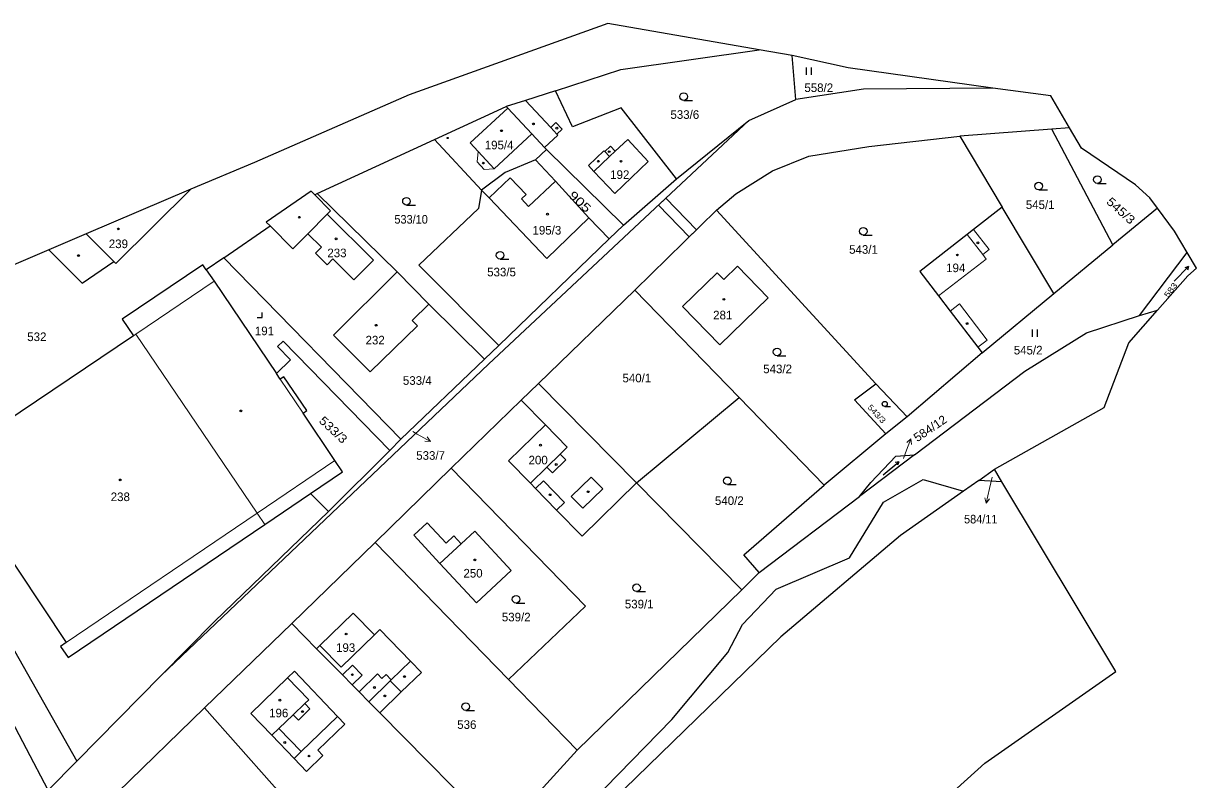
# Model space of a CAD drawing. Extents: x -754445 to -751443, y -1030748 to -1028224.
# Drawn here: x -752550.8 to -752319, y -1028439.3 to -1028289.9 of the extents above; entities that cross this region are included whole.
import ezdxf
from ezdxf.enums import TextEntityAlignment as Align

# ---------------------------------------------------------------- set-up
doc = ezdxf.new("R2010")
doc.units = 0
doc.header["$LTSCALE"] = 0.68
for name, color, linetype, lineweight in [('1', 7, 'Continuous', 25), ('13', 7, 'Continuous', 13), ('3', 7, 'Continuous', 25), ('4', 7, 'Continuous', 13), ('5', 7, 'Continuous', 25), ('7', 7, 'Continuous', 13)]:
    doc.layers.add(name, color=color, linetype=linetype, lineweight=lineweight)
doc.layers.add('2', color=7, linetype='Continuous')

msp = doc.modelspace()

# ---------------------------------------------------------------- linework, layer by layer
at = {"layer": '1'}
for p, q in [((-752398.89, -1028296.26), (-752405.38, -1028295.13)), ((-752387.84, -1028298.72), (-752398.89, -1028296.26)), ((-752359.23, -1028302.73), (-752387.84, -1028298.72)), ((-752469.6, -1028312.88), (-752455.4, -1028306.37)), ((-752469.6, -1028312.88), (-752460.28, -1028322.85)), ((-752449.62, -1028316.91), (-752447.46, -1028314.86)), ((-752455.63, -1028319.39), (-752460.28, -1028322.85)), ((-752476.98, -1028339.02), (-752492.8, -1028323.52)), ((-752430.02, -1028342.61), (-752413.84, -1028326.86)), ((-752511.23, -1028336.26), (-752502.09, -1028329.94)), ((-752435.06, -1028332.52), (-752439.06, -1028328.33)), ((-752432.25, -1028329.82), (-752435.06, -1028332.52)), ((-752456.89, -1028353.54), (-752435.06, -1028332.52)), ((-752330.24, -1028347.65), (-752320.82, -1028335.2)), ((-752470.68, -1028345.38), (-752476.98, -1028339.02)), ((-752430.02, -1028342.61), (-752449.02, -1028361.08)), ((-752330.24, -1028347.65), (-752326.68, -1028346.62)), ((-752456.89, -1028353.54), (-752459.73, -1028356.27)), ((-752386.55, -1028364.28), (-752382.36, -1028361.14)), ((-752452.44, -1028364.4), (-752466.28, -1028377.84)), ((-752392.57, -1028381.17), (-752409.39, -1028363.85)), ((-752380.37, -1028371.03), (-752386.55, -1028364.28)), ((-752490.54, -1028386.35), (-752478.41, -1028374.3)), ((-752374.74, -1028375.19), (-752385.55, -1028383.4)), ((-752466.28, -1028377.84), (-752481.34, -1028392.48)), ((-752357.44, -1028380.49), (-752358.91, -1028378.04)), ((-752405.38, -1028398.45), (-752385.55, -1028383.4)), ((-752481.34, -1028392.48), (-752497.81, -1028408.48)), ((-752454.95, -1028419.58), (-752481.34, -1028392.48)), ((-752408.87, -1028401.85), (-752405.38, -1028398.45)), ((-752540.27, -1028435.69), (-752523.59, -1028418.77)), ((-752441.39, -1028433.5), (-752454.95, -1028419.58)), ((-752532.24, -1028441.9), (-752515.04, -1028425.14)), ((-752456.6, -1028450.26), (-752441.39, -1028433.5)), ((-752540.27, -1028435.69), (-752545.95, -1028441.45))]:
    msp.add_line(p, q, dxfattribs=at)
for points in [[(-752405.38, -1028295.13), (-752435.3, -1028289.94), (-752474.61, -1028304.07), (-752505.18, -1028317.44), (-752517.76, -1028322.7)], [(-752445.69, -1028303.22), (-752432.77, -1028299.03), (-752405.38, -1028295.13)], [(-752421.72, -1028320.62), (-752407.46, -1028309.12), (-752398.17, -1028304.98), (-752398.89, -1028296.26)], [(-752445.69, -1028303.22), (-752451.62, -1028305.14), (-752455.4, -1028306.37)], [(-752421.72, -1028320.62), (-752432.69, -1028306.58), (-752442.28, -1028310.36), (-752445.69, -1028303.22)], [(-752359.23, -1028302.73), (-752384.8, -1028302.94), (-752398.17, -1028304.98)], [(-752344.05, -1028310.59), (-752347.75, -1028304.24), (-752359.23, -1028302.73)], [(-752455.4, -1028306.37), (-752455.1, -1028306.68), (-752450.34, -1028311.78), (-752447.82, -1028314.48), (-752447.46, -1028314.86), (-752432.25, -1028329.82), (-752421.72, -1028320.62)], [(-752523.59, -1028418.77), (-752458.89, -1028357.28), (-752407.46, -1028309.12)], [(-752347.15, -1028343.32), (-752335.5, -1028333.7), (-752347.54, -1028310.85), (-752365.74, -1028312.22), (-752357.35, -1028326.26)], [(-752326.68, -1028326.41), (-752328.18, -1028324.37), (-752331.04, -1028321.82), (-752341.71, -1028314.6), (-752344.05, -1028310.59), (-752347.54, -1028310.85)], [(-752493.24, -1028323.83), (-752492.8, -1028323.52), (-752469.6, -1028312.88)], [(-752413.84, -1028326.86), (-752410.04, -1028323.61), (-752402.77, -1028319.05), (-752395.61, -1028316.19), (-752383.74, -1028314.26), (-752365.74, -1028312.22)], [(-752439.06, -1028328.33), (-752445.67, -1028321.09), (-752449.62, -1028316.91), (-752455.63, -1028319.39)], [(-752517.76, -1028322.7), (-752538.45, -1028331.51), (-752545.81, -1028334.65)], [(-752545.81, -1028334.65), (-752539.2, -1028341.26), (-752532.94, -1028336.98), (-752532.55, -1028337.37), (-752517.76, -1028322.7)], [(-752460.28, -1028322.85), (-752460.92, -1028326.51), (-752472.66, -1028337.69), (-752456.89, -1028353.54)], [(-752439.06, -1028328.33), (-752447.39, -1028336.38), (-752458.79, -1028324.4), (-752460.28, -1028322.85)], [(-752493.24, -1028323.83), (-752493.97, -1028323.1), (-752502.86, -1028329.17), (-752502.09, -1028329.94)], [(-752502.09, -1028329.94), (-752497.59, -1028334.44), (-752494.6, -1028331.48), (-752491.95, -1028334.14), (-752493.11, -1028335.3), (-752490.81, -1028337.6), (-752489.65, -1028336.44), (-752485.51, -1028340.57), (-752481.66, -1028336.71), (-752490.77, -1028327.61), (-752490.11, -1028326.95), (-752493.24, -1028323.83)], [(-752413.84, -1028326.86), (-752382.36, -1028361.14), (-752376.18, -1028367.69)], [(-752357.35, -1028326.26), (-752363.03, -1028330.68), (-752364.29, -1028331.67), (-752373.64, -1028338.95), (-752369.96, -1028343.75), (-752367.65, -1028346.76), (-752362.18, -1028353.9), (-752361.32, -1028355.02)], [(-752361.32, -1028355.02), (-752347.15, -1028343.32), (-752357.35, -1028326.26)], [(-752320.82, -1028335.2), (-752323.33, -1028330.97), (-752326.68, -1028326.41), (-752335.5, -1028333.7)], [(-752545.81, -1028334.65), (-752556.51, -1028339.21), (-752568.95, -1028351.49), (-752579.96, -1028370.78)], [(-752500.83, -1028359.1), (-752498.05, -1028356.39), (-752500.59, -1028353.77), (-752499.48, -1028352.69), (-752478.41, -1028374.3), (-752476.21, -1028372.11), (-752511.23, -1028336.26), (-752514.69, -1028338.65)], [(-752326.68, -1028346.62), (-752320.66, -1028339.81), (-752318.96, -1028338.32), (-752320.82, -1028335.2)], [(-752514.69, -1028338.65), (-752515.41, -1028337.64), (-752531.29, -1028348.38), (-752529.08, -1028351.68), (-752561.06, -1028373.16), (-752562.37, -1028371.21), (-752567.41, -1028374.68), (-752566.1, -1028376.62), (-752542.38, -1028412.28), (-752543.51, -1028413.04), (-752542.01, -1028415.25), (-752503.1, -1028388.94), (-752494.07, -1028382.8)], [(-752514.69, -1028338.65), (-752513.11, -1028340.87), (-752500.83, -1028359.1)], [(-752476.98, -1028339.02), (-752489.54, -1028351.55), (-752482.27, -1028358.76), (-752472.95, -1028349.66), (-752473.98, -1028348.6), (-752470.68, -1028345.38)], [(-752429.66, -1028380.74), (-752409.39, -1028363.85), (-752430.02, -1028342.61)], [(-752476.21, -1028372.11), (-752459.73, -1028356.27), (-752470.68, -1028345.38)], [(-752374.74, -1028375.19), (-752352.93, -1028358.63), (-752340.68, -1028351.04), (-752330.24, -1028347.65)], [(-752337.25, -1028365.83), (-752332.34, -1028353.02), (-752326.68, -1028346.62)], [(-752361.32, -1028355.02), (-752376.18, -1028367.69), (-752380.37, -1028371.03), (-752392.57, -1028381.17)], [(-752494.07, -1028382.8), (-752487.77, -1028378.51), (-752489.26, -1028376.3), (-752495.53, -1028366.91), (-752494.82, -1028366.42), (-752499.36, -1028359.74), (-752500.07, -1028360.23), (-752500.83, -1028359.1)], [(-752429.66, -1028380.74), (-752449.02, -1028361.08), (-752452.44, -1028364.4)], [(-752452.44, -1028364.4), (-752447.67, -1028369.27), (-752454.94, -1028376.39), (-752450.62, -1028380.8), (-752449.61, -1028381.84), (-752445.45, -1028386.08), (-752440.39, -1028391.25), (-752429.66, -1028380.74)], [(-752362.02, -1028380.23), (-752358.91, -1028378.04), (-752337.25, -1028365.83)], [(-752584.13, -1028375.9), (-752579.37, -1028374.82), (-752573.06, -1028377.89), (-752540.27, -1028435.69)], [(-752385.55, -1028383.4), (-752383.32, -1028380.64), (-752378.37, -1028375.43), (-752374.74, -1028375.19)], [(-752466.28, -1028377.84), (-752439.77, -1028405.07), (-752454.95, -1028419.58)], [(-752529.24, -1028502.86), (-752525.84, -1028499.97), (-752501.12, -1028496.21), (-752473.43, -1028475.03), (-752455.24, -1028458.91), (-752438.5, -1028443.67), (-752422.66, -1028427.47), (-752411.63, -1028414.26), (-752408.72, -1028408.7), (-752402.05, -1028401.7), (-752387.55, -1028395.51), (-752380.84, -1028384.53), (-752373.02, -1028380.06), (-752365.04, -1028382.36)], [(-752441.39, -1028433.5), (-752408.87, -1028401.85), (-752429.66, -1028380.74)], [(-752334.93, -1028417.99), (-752357.44, -1028380.49), (-752362.02, -1028380.23), (-752365.04, -1028382.36)], [(-752365.04, -1028382.36), (-752377.46, -1028391.11), (-752401.11, -1028411.16), (-752446.33, -1028455.06), (-752461.39, -1028474.9), (-752481.91, -1028492.23), (-752531.14, -1028512.51)], [(-752523.59, -1028418.77), (-752513.07, -1028408.1), (-752490.54, -1028386.35), (-752494.07, -1028382.8)], [(-752405.38, -1028398.45), (-752408.43, -1028394.94), (-752392.57, -1028381.17)], [(-752575.39, -1028472.41), (-752545.95, -1028441.45), (-752567.4, -1028400.59)], [(-752480.38, -1028426.15), (-752476.15, -1028422.03), (-752472.17, -1028418.16), (-752474.33, -1028415.93), (-752480.4, -1028409.7), (-752481.47, -1028410.75), (-752485.66, -1028406.45), (-752492.24, -1028412.86), (-752492.88, -1028413.48)], [(-752492.88, -1028413.48), (-752497.81, -1028408.48), (-752515.04, -1028425.14), (-752475.1, -1028470.2), (-752465.01, -1028461.38)], [(-752492.88, -1028413.48), (-752487.75, -1028418.68), (-752485.85, -1028420.6), (-752484.45, -1028422.03), (-752482.55, -1028423.95), (-752480.38, -1028426.15)], [(-752383.33, -1028456.44), (-752360.81, -1028436.09), (-752334.93, -1028417.99)], [(-752465.01, -1028461.38), (-752456.6, -1028450.26), (-752480.38, -1028426.15)]]:
    msp.add_lwpolyline(points, dxfattribs=at)
for points in [[(-752403.61, -1028344.14), (-752413.17, -1028353.43), (-752420.54, -1028345.85), (-752413.69, -1028339.22), (-752412.4, -1028340.55), (-752409.67, -1028337.91)], [(-752468.51, -1028396.62), (-752461.31, -1028404.4), (-752454.43, -1028398.04), (-752461.63, -1028390.26), (-752464.31, -1028392.73), (-752465.75, -1028391.18), (-752467.29, -1028392.6), (-752471.01, -1028388.58), (-752473.67, -1028391.04)], [(-752498.64, -1028419.21), (-752505.89, -1028426.26), (-752501.72, -1028430.6), (-752497.35, -1028435.15), (-752494.87, -1028437.73), (-752491.63, -1028434.61), (-752492.66, -1028433.53), (-752487.34, -1028428.39), (-752488.78, -1028426.87), (-752497.28, -1028417.89)]]:
    msp.add_lwpolyline(points, close=True, dxfattribs=at)
at = {"layer": '13'}
msp.add_lwpolyline([(-752417.82, -1028330.73), (-752423.83, -1028324.45), (-752425.29, -1028325.82), (-752419.25, -1028332.13)], close=True, dxfattribs=at)
at = {"layer": '3'}
for p, q in [((-752396.071, -1028300.11), (-752396.071, -1028298.61)), ((-752395.07, -1028300.11), (-752395.07, -1028298.61)), ((-752420.333, -1028305.13), (-752418.583, -1028305.13)), ((-752350.163, -1028322.82), (-752348.413, -1028322.82)), ((-752338.563, -1028321.55), (-752336.813, -1028321.55)), ((-752475.123, -1028325.83), (-752473.373, -1028325.83)), ((-752384.833, -1028331.75), (-752383.083, -1028331.75)), ((-752456.633, -1028336.5), (-752454.883, -1028336.5)), ((-752320.562, -1028337.98), (-752320.775, -1028338.684)), ((-752351.381, -1028351.88), (-752351.381, -1028350.38)), ((-752350.38, -1028351.88), (-752350.38, -1028350.38)), ((-752401.873, -1028355.59), (-752400.123, -1028355.59)), ((-752380.595, -1028365.63), (-752379.423, -1028365.63)), ((-752377.808, -1028376.535), (-752378.093, -1028377.213)), ((-752411.683, -1028381.06), (-752409.933, -1028381.06)), ((-752429.643, -1028402.18), (-752427.893, -1028402.18)), ((-752453.453, -1028404.47), (-752451.703, -1028404.47)), ((-752463.403, -1028425.67), (-752461.653, -1028425.67))]:
    msp.add_line(p, q, dxfattribs=at)
for points in [[(-752323.354, -1028340.872), (-752320.562, -1028337.98), (-752321.258, -1028338.217)], [(-752504.621, -1028348.06), (-752503.62, -1028348.06), (-752503.62, -1028347.06)], [(-752380.887, -1028379.119), (-752377.808, -1028376.535), (-752378.525, -1028376.698)]]:
    msp.add_lwpolyline(points, dxfattribs=at)
for centre, radius in [((-752420.3329, -1028304.3798), 0.75), ((-752338.5629, -1028320.7998), 0.75), ((-752350.1629, -1028322.0698), 0.75), ((-752475.1229, -1028325.0798), 0.75), ((-752384.8329, -1028330.9998), 0.75), ((-752456.6329, -1028335.7498), 0.75), ((-752401.8729, -1028354.8398), 0.75), ((-752380.5952, -1028365.1274), 0.5025), ((-752411.6829, -1028380.3098), 0.75), ((-752429.6429, -1028401.4298), 0.75), ((-752453.4529, -1028403.7198), 0.75), ((-752463.4029, -1028424.9198), 0.75)]:
    msp.add_circle(centre, radius, dxfattribs=at)
at = {"layer": '4'}
for p, q in [((-752455.1, -1028306.68), (-752462.53, -1028313.55)), ((-752451.62, -1028305.14), (-752446.62, -1028310.48)), ((-752446.62, -1028310.48), (-752445.6, -1028309.53)), ((-752446.62, -1028310.48), (-752445.39, -1028311.8)), ((-752445.6, -1028309.53), (-752444.37, -1028310.84)), ((-752444.37, -1028310.84), (-752445.39, -1028311.8)), ((-752462.53, -1028313.55), (-752460.94, -1028315.27)), ((-752457.8, -1028318.68), (-752450.34, -1028311.78)), ((-752445.19, -1028312.02), (-752447.82, -1028314.48)), ((-752445.39, -1028311.8), (-752445.19, -1028312.02)), ((-752433.85, -1028315.2), (-752431.38, -1028312.89)), ((-752427.33, -1028317.22), (-752431.38, -1028312.89)), ((-752460.94, -1028315.27), (-752461.15, -1028317.3)), ((-752460.94, -1028315.27), (-752457.8, -1028318.68)), ((-752436.1, -1028315.08), (-752439.17, -1028318.01)), ((-752435.94, -1028315.24), (-752436.1, -1028315.08)), ((-752435.94, -1028315.24), (-752434.8, -1028314.18)), ((-752434.98, -1028316.25), (-752435.94, -1028315.24)), ((-752434.98, -1028316.25), (-752433.85, -1028315.2)), ((-752434.8, -1028314.18), (-752433.85, -1028315.2)), ((-752461.15, -1028317.3), (-752459.78, -1028318.79)), ((-752439.17, -1028318.01), (-752438.08, -1028319.16)), ((-752438.08, -1028319.16), (-752434.98, -1028316.25)), ((-752433.93, -1028323.51), (-752427.33, -1028317.22)), ((-752459.78, -1028318.79), (-752457.8, -1028318.68)), ((-752454.61, -1028320.44), (-752458.79, -1028324.4)), ((-752451.49, -1028323.74), (-752454.61, -1028320.44)), ((-752438.08, -1028319.16), (-752433.93, -1028323.51)), ((-752445.67, -1028321.09), (-752450.99, -1028326.13)), ((-752452.41, -1028324.62), (-752451.49, -1028323.74)), ((-752450.99, -1028326.13), (-752452.41, -1028324.62)), ((-752494.6, -1028331.48), (-752490.77, -1028327.61)), ((-752538.45, -1028331.51), (-752532.94, -1028336.98)), ((-752361.23, -1028335.61), (-752364.29, -1028331.67)), ((-752363.03, -1028330.68), (-752359.96, -1028334.62)), ((-752359.96, -1028334.62), (-752361.23, -1028335.61)), ((-752360.52, -1028336.51), (-752369.96, -1028343.75)), ((-752360.52, -1028336.51), (-752361.23, -1028335.61)), ((-752528.59, -1028351.35), (-752513.11, -1028340.87)), ((-752365.83, -1028345.36), (-752367.65, -1028346.76)), ((-752360.35, -1028352.5), (-752365.83, -1028345.36)), ((-752528.59, -1028351.35), (-752529.08, -1028351.68)), ((-752504.63, -1028386.68), (-752528.59, -1028351.35)), ((-752360.35, -1028352.5), (-752362.18, -1028353.9)), ((-752495.53, -1028366.91), (-752500.07, -1028360.23)), ((-752443.35, -1028373.68), (-752447.67, -1028369.27)), ((-752444.74, -1028375.04), (-752443.35, -1028373.68)), ((-752504.63, -1028386.68), (-752489.26, -1028376.3)), ((-752447.38, -1028377.63), (-752444.74, -1028375.04)), ((-752446.29, -1028378.75), (-752443.64, -1028376.16)), ((-752443.64, -1028376.16), (-752444.74, -1028375.04)), ((-752450.62, -1028380.8), (-752447.38, -1028377.63)), ((-752447.38, -1028377.63), (-752446.29, -1028378.75)), ((-752448.07, -1028380.33), (-752449.61, -1028381.84)), ((-752443.92, -1028384.57), (-752448.07, -1028380.33)), ((-752442.55, -1028383.42), (-752438.61, -1028379.56)), ((-752438.61, -1028379.56), (-752436.34, -1028381.89)), ((-752436.34, -1028381.89), (-752440.28, -1028385.74)), ((-752445.45, -1028386.08), (-752443.92, -1028384.57)), ((-752440.28, -1028385.74), (-752442.55, -1028383.42)), ((-752542.38, -1028412.28), (-752504.63, -1028386.68)), ((-752503.1, -1028388.94), (-752504.63, -1028386.68)), ((-752468.51, -1028396.62), (-752464.31, -1028392.73)), ((-752488.05, -1028417.16), (-752481.47, -1028410.75)), ((-752488.05, -1028417.16), (-752492.24, -1028412.86)), ((-752485.79, -1028416.77), (-752487.75, -1028418.68)), ((-752483.91, -1028418.71), (-752485.79, -1028416.77)), ((-752478.12, -1028419.63), (-752474.33, -1028415.93)), ((-752498.64, -1028419.21), (-752494.45, -1028423.57)), ((-752485.85, -1028420.6), (-752483.91, -1028418.71)), ((-752480.85, -1028418.48), (-752484.45, -1028422.03)), ((-752482.55, -1028423.95), (-752478.32, -1028419.82)), ((-752480.85, -1028418.48), (-752479.99, -1028419.36)), ((-752479.99, -1028419.36), (-752479.17, -1028418.56)), ((-752479.17, -1028418.56), (-752478.12, -1028419.63)), ((-752478.32, -1028419.82), (-752478.12, -1028419.63)), ((-752478.32, -1028419.82), (-752476.15, -1028422.03)), ((-752495.24, -1028424.34), (-752497.52, -1028426.54)), ((-752495.24, -1028424.34), (-752494.45, -1028423.57)), ((-752494.22, -1028425.39), (-752495.24, -1028424.34)), ((-752500.33, -1028429.25), (-752497.52, -1028426.54)), ((-752497.52, -1028426.54), (-752496.5, -1028427.6)), ((-752496.5, -1028427.6), (-752494.22, -1028425.39)), ((-752495.95, -1028433.8), (-752488.78, -1028426.87)), ((-752501.72, -1028430.6), (-752500.33, -1028429.25)), ((-752500.33, -1028429.25), (-752495.95, -1028433.8)), ((-752495.95, -1028433.8), (-752497.35, -1028435.15))]:
    msp.add_line(p, q, dxfattribs=at)
at = {"layer": '5'}
for centre, radius in [((-752456.3468, -1028311.1392), 0.175), ((-752450.0368, -1028309.7892), 0.175), ((-752445.3968, -1028310.6192), 0.175), ((-752466.9746, -1028312.5694), 0.1172), ((-752435.0368, -1028315.2692), 0.175), ((-752459.9368, -1028317.5292), 0.175), ((-752437.2068, -1028317.1692), 0.175), ((-752432.7168, -1028317.1692), 0.175), ((-752447.2568, -1028327.6292), 0.175), ((-752496.3068, -1028328.2292), 0.175), ((-752532.0868, -1028330.5392), 0.175), ((-752489.0468, -1028332.4992), 0.175), ((-752362.1668, -1028333.2892), 0.175), ((-752539.9468, -1028335.7992), 0.175), ((-752366.2368, -1028335.6892), 0.175), ((-752412.3768, -1028344.4492), 0.175), ((-752481.1168, -1028349.5792), 0.175), ((-752364.3168, -1028349.2392), 0.175), ((-752507.8468, -1028366.4992), 0.175), ((-752448.6368, -1028373.2592), 0.175), ((-752445.5168, -1028377.0792), 0.175), ((-752531.6968, -1028380.1292), 0.175), ((-752446.7468, -1028383.0592), 0.175), ((-752439.2168, -1028382.4692), 0.175), ((-752461.5968, -1028395.9392), 0.175), ((-752487.0668, -1028410.5792), 0.175), ((-752485.8268, -1028418.6192), 0.175), ((-752475.5168, -1028418.9892), 0.175), ((-752481.4568, -1028421.1492), 0.175), ((-752479.3968, -1028422.8092), 0.175), ((-752500.1468, -1028423.6492), 0.175), ((-752495.6868, -1028425.9092), 0.175), ((-752499.1868, -1028432.0092), 0.175), ((-752494.3868, -1028434.6892), 0.175)]:
    msp.add_circle(centre, radius, dxfattribs=at)
at = {"layer": '7'}
for p, q in [((-752470.375, -1028372.515), (-752471.008, -1028371.591)), ((-752375.415, -1028371.998), (-752376.241, -1028372.754)), ((-752360.565, -1028384.744), (-752359.852, -1028383.881))]:
    msp.add_line(p, q, dxfattribs=at)
for points in [[(-752473.86, -1028370.59), (-752473, -1028371.06), (-752470.375, -1028372.515), (-752471.494, -1028372.467)], [(-752376.9, -1028375.88), (-752376.49, -1028374.8), (-752375.415, -1028371.998), (-752375.306, -1028373.113)], [(-752359.37, -1028379.57), (-752359.89, -1028381.82), (-752360.565, -1028384.744), (-752360.828, -1028383.656)]]:
    msp.add_lwpolyline(points, dxfattribs=at)

# ---------------------------------------------------------------- texts
at = {"layer": '2'}
for s, p in [('558/2', (-752393.63, -1028303.49)), ('533/6', (-752420.11, -1028308.79)), ('195/4', (-752456.81, -1028314.81)), ('192', (-752432.969, -1028320.66)), ('545/1', (-752349.86, -1028326.61)), ('195/3', (-752447.37, -1028331.65)), ('239', (-752532.069, -1028334.33)), ('233', (-752488.869, -1028336.13)), ('543/1', (-752384.79, -1028335.45)), ('533/5', (-752456.33, -1028339.91)), ('194', (-752366.559, -1028339.08)), ('281', (-752412.609, -1028348.41)), ('191', (-752503.199, -1028351.54)), ('532', (-752548.189, -1028352.7)), ('232', (-752481.319, -1028353.36)), ('545/2', (-752352.24, -1028355.34)), ('543/2', (-752401.77, -1028359.05)), ('533/4', (-752472.99, -1028361.34)), ('540/1', (-752429.59, -1028360.85)), ('200', (-752449.099, -1028377.06)), ('238', (-752531.689, -1028384.32)), ('540/2', (-752411.31, -1028385.08)), ('250', (-752461.969, -1028399.42)), ('539/1', (-752429.12, -1028405.52)), ('539/2', (-752453.43, -1028408.08)), ('193', (-752487.149, -1028414.12)), ('196', (-752500.379, -1028427.04)), ('536', (-752463.199, -1028429.33))]:
    msp.add_text(s, height=1.7, dxfattribs=at).set_placement(p, align=Align.CENTER)
for s, height, rotation, width, p in [('905', 1.7, 317, 1.3, (-752441.4132, -1028325.7813)), ('545/3', 1.7, 318, 1.15, (-752334.4888, -1028327.5622)), ('583', 1.14, 53, 1.25, (-752323.6216, -1028342.9535)), ('543/3', 1.14, 313, 1.15, (-752382.595, -1028367.4773)), ('533/3', 1.7, 317, 1.15, (-752490.1732, -1028370.8518))]:
    msp.add_text(s, height=height, rotation=rotation, dxfattribs=dict(at, width=width)).set_placement(p, align=Align.CENTER)
at = {"layer": '2', "width": 0.95}
msp.add_text('533/10', height=1.7, dxfattribs=at).set_placement((-752474.209, -1028329.49), align=Align.CENTER)
at = {"layer": '2', "width": 1.05}
msp.add_text('584/12', height=1.7, rotation=34, dxfattribs=at).set_placement((-752374.164, -1028372.704))
at = {"layer": '2'}
msp.add_text('533/7', height=1.7, dxfattribs=at).set_placement((-752473.2, -1028376.153))
at = {"layer": '2', "width": 0.95}
msp.add_text('584/11', height=1.7, dxfattribs=at).set_placement((-752358.31, -1028388.733), align=Align.RIGHT)

doc.saveas('drawing.dxf')
